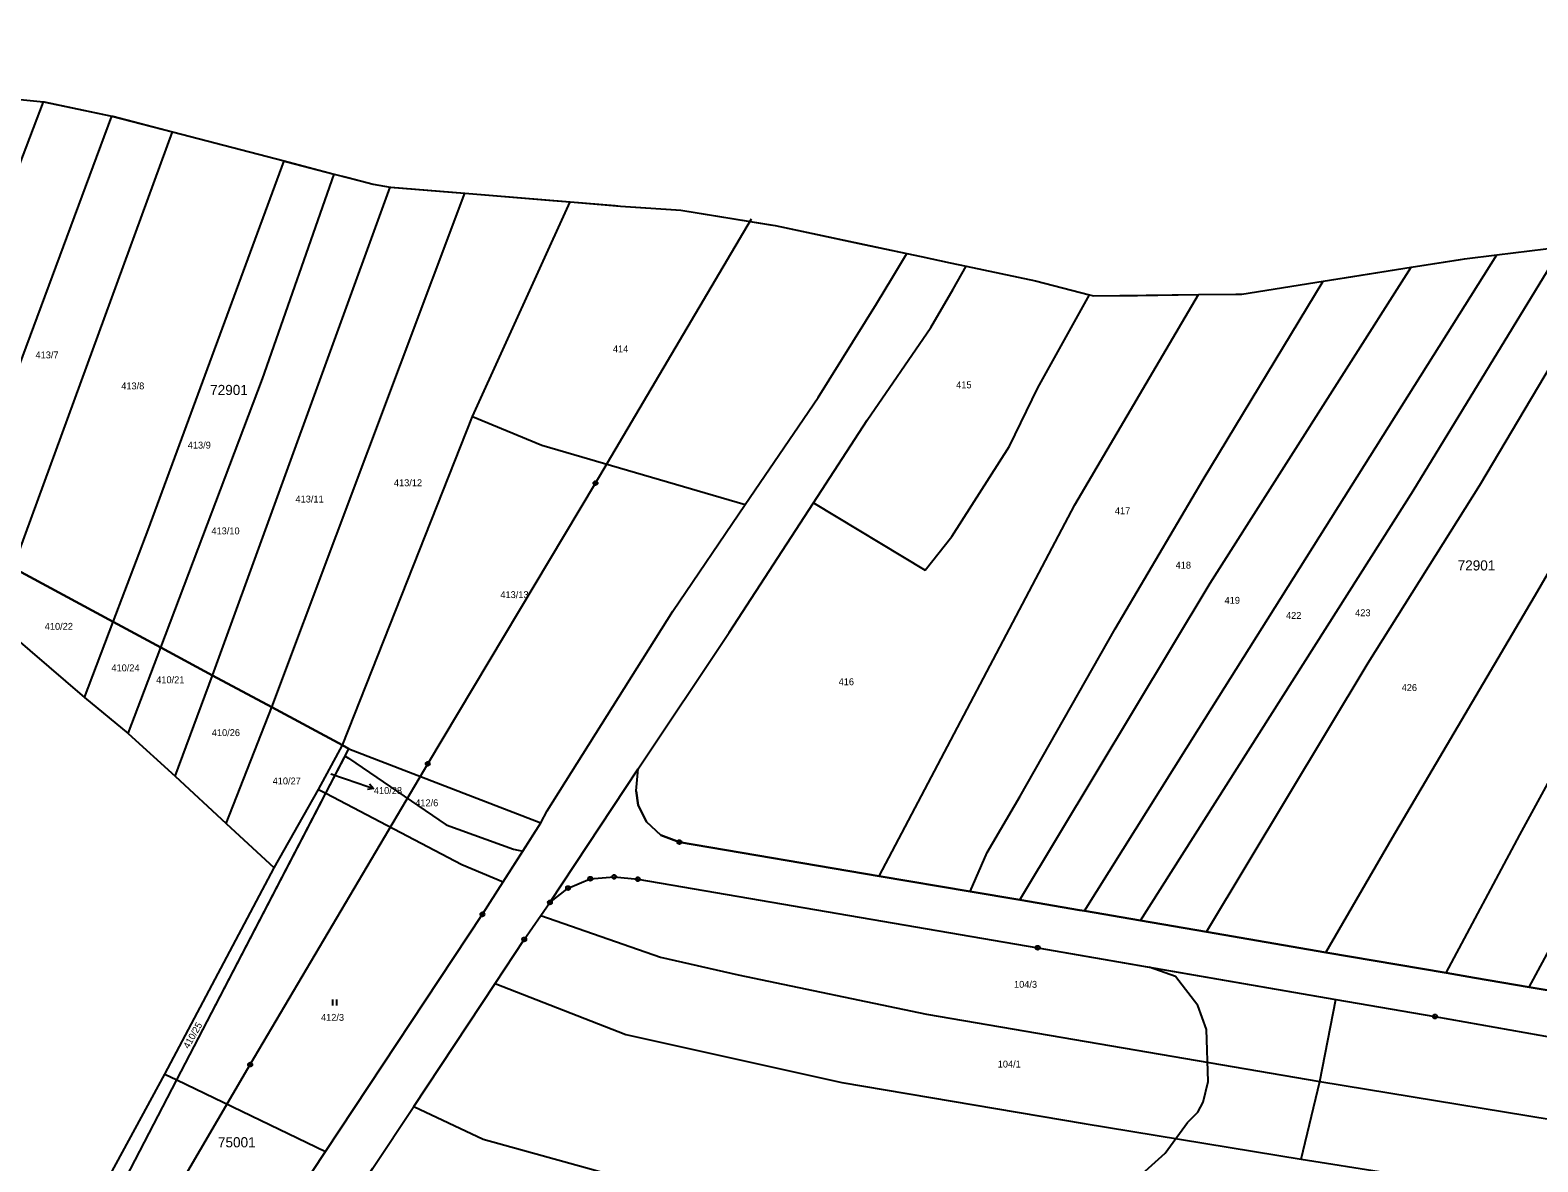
# Model space of a CAD drawing. Extents: x -743888 to -742027, y -1128394 to -1126768.
# Drawn here: x -743633.6 to -743261.6, y -1127120.7 to -1126841.6 of the extents above; entities that cross this region are included whole.
import ezdxf

# ---------------------------------------------------------------- set-up
doc = ezdxf.new("R2010")
doc.units = 0
for name, color, linetype in [('Vrstva 1', 7, 'Continuous'), ('Vrstva 12', 7, 'Continuous'), ('Vrstva 13', 7, 'Continuous'), ('Vrstva 16', 7, 'Continuous'), ('Vrstva 18', 7, 'Continuous'), ('Vrstva 24', 7, 'Continuous'), ('Vrstva 25', 7, 'Continuous'), ('Vrstva 26', 7, 'Continuous'), ('Vrstva 52', 7, 'Continuous'), ('Vrstva 53', 7, 'Continuous'), ('Vrstva 6', 7, 'Continuous')]:
    doc.layers.add(name, color=color, linetype=linetype)

msp = doc.modelspace()

# ---------------------------------------------------------------- linework, layer by layer
at = {"layer": 'Vrstva 1'}
for points in [[(-743420.79, -1126902.49), (-743417.33, -1126896.72)], [(-743405.93, -1126905.47), (-743402.66, -1126899.83)], [(-743424.78, -1126909.13), (-743420.79, -1126902.49)], [(-743411.38, -1126914.91), (-743405.93, -1126905.47)], [(-743439.2, -1126932.19), (-743424.78, -1126909.13)], [(-743427.08, -1126937.82), (-743411.38, -1126914.91)], [(-743457.17, -1126958.62), (-743439.2, -1126932.19)], [(-743440.35, -1126958.18), (-743427.08, -1126937.82)], [(-743475.03, -1126984.89), (-743457.17, -1126958.62)], [(-743461.19, -1126990.18), (-743440.35, -1126958.18)], [(-743637.84, -1126974.2), (-743613.12, -1126987.52)], [(-743506.07, -1127034.13), (-743475.03, -1126984.89)], [(-743613.12, -1126987.52), (-743601.38, -1126993.85)], [(-743483.62, -1127023.79), (-743461.19, -1126990.18)], [(-743601.38, -1126993.85), (-743588.59, -1127000.75)], [(-743588.59, -1127000.75), (-743573.98, -1127008.62)], [(-743573.98, -1127008.62), (-743556.57, -1127018)], [(-743560.68, -1127029.82), (-743554.98, -1127018.86)], [(-743556.57, -1127018), (-743554.98, -1127018.86)], [(-743554.98, -1127018.86), (-743507.61, -1127037.13)], [(-743505.37, -1127056.75), (-743483.62, -1127023.79)], [(-743484.09, -1127029.22), (-743483.62, -1127023.79)], [(-743597.45, -1127100.54), (-743560.68, -1127029.82)], [(-743484.09, -1127029.22), (-743483.64, -1127032.8)], [(-743483.64, -1127032.8), (-743481.55, -1127036.83)], [(-743516.89, -1127051.64), (-743507.61, -1127037.13)], [(-743507.61, -1127037.13), (-743506.07, -1127034.13)], [(-743481.55, -1127036.83), (-743477.98, -1127040.17)], [(-743477.98, -1127040.17), (-743473.44, -1127041.87)], [(-743473.44, -1127041.87), (-743424.12, -1127050.25)], [(-743522.03, -1127059.68), (-743516.89, -1127051.64)], [(-743500.91, -1127053.2), (-743495.43, -1127050.9)], [(-743495.43, -1127050.9), (-743489.52, -1127050.44)], [(-743489.52, -1127050.44), (-743483.7, -1127051.01)], [(-743483.7, -1127051.01), (-743385.04, -1127067.93)], [(-743424.12, -1127050.25), (-743401.72, -1127054.05)], [(-743505.37, -1127056.75), (-743500.91, -1127053.2)], [(-743401.72, -1127054.05), (-743389.47, -1127056.13)], [(-743389.47, -1127056.13), (-743374.75, -1127058.63)], [(-743560.72, -1127118.19), (-743522.03, -1127059.68)], [(-743511.71, -1127065.87), (-743507.61, -1127059.97)], [(-743507.61, -1127059.97), (-743505.37, -1127056.75)], [(-743374.75, -1127058.63), (-743373.46, -1127058.85)], [(-743373.46, -1127058.85), (-743359.71, -1127061.21)], [(-743359.71, -1127061.21), (-743343.4, -1127064.01)], [(-743518.91, -1127076.75), (-743511.71, -1127065.87)], [(-743343.4, -1127064.01), (-743313.92, -1127069.06)], [(-743385.04, -1127067.93), (-743311.47, -1127080.65)], [(-743313.92, -1127069.06), (-743284.26, -1127074.14)], [(-743284.26, -1127074.14), (-743277.29, -1127075.34)], [(-743538.97, -1127107.07), (-743518.91, -1127076.75)], [(-743277.29, -1127075.34), (-743263.8, -1127077.63)], [(-743263.8, -1127077.63), (-743251.53, -1127079.71)], [(-743311.47, -1127080.65), (-743287.04, -1127084.88)], [(-743287.04, -1127084.88), (-743198.26, -1127100.66)], [(-743642.12, -1127186.45), (-743597.45, -1127100.54)], [(-743549.04, -1127122.29), (-743538.97, -1127107.07)], [(-743576.94, -1127142.72), (-743560.72, -1127118.19)]]:
    msp.add_lwpolyline(points, dxfattribs=at)
at = {"layer": 'Vrstva 12'}
for points in [[(-743494.14, -1126953.33), (-743455.61, -1126888.13)], [(-743535.51, -1127022.55), (-743494.14, -1126953.33)], [(-743579.34, -1127096.74), (-743535.51, -1127022.55)], [(-743624.66, -1127174.21), (-743579.34, -1127096.74)]]:
    msp.add_lwpolyline(points, dxfattribs=at)
at = {"layer": 'Vrstva 13'}
for points in [[(-743658.2, -1126856.48), (-743630.32, -1126859.26)], [(-743630.32, -1126859.26), (-743626.75, -1126860)], [(-743626.75, -1126860), (-743613.43, -1126862.82)], [(-743613.43, -1126862.82), (-743598.46, -1126866.7)], [(-743598.46, -1126866.7), (-743570.98, -1126873.86)], [(-743570.98, -1126873.86), (-743570.28, -1126874.05)], [(-743570.28, -1126874.05), (-743558.58, -1126877.09)], [(-743558.58, -1126877.09), (-743555.26, -1126877.96)], [(-743555.26, -1126877.96), (-743548.99, -1126879.59)], [(-743548.99, -1126879.59), (-743544.8, -1126880.33)], [(-743544.8, -1126880.33), (-743529.54, -1126881.59)], [(-743529.54, -1126881.59), (-743526.35, -1126881.85)], [(-743526.35, -1126881.85), (-743516.49, -1126882.66)], [(-743516.49, -1126882.66), (-743504.64, -1126883.63)], [(-743504.64, -1126883.63), (-743500.35, -1126883.98)], [(-743500.35, -1126883.98), (-743489.25, -1126884.88)], [(-743489.25, -1126884.88), (-743487.94, -1126884.99)], [(-743487.94, -1126884.99), (-743474.2, -1126885.91)], [(-743474.2, -1126885.91), (-743473.08, -1126885.98)], [(-743473.08, -1126885.98), (-743451, -1126889.6)], [(-743451, -1126889.6), (-743449.81, -1126889.8)], [(-743449.81, -1126889.8), (-743427.91, -1126894.47)], [(-743427.91, -1126894.47), (-743417.33, -1126896.72)], [(-743271.77, -1126897.03), (-743255.64, -1126895.06)], [(-743417.33, -1126896.72), (-743413.79, -1126897.47)], [(-743413.79, -1126897.47), (-743406.62, -1126898.99)], [(-743406.62, -1126898.99), (-743402.66, -1126899.83)], [(-743402.66, -1126899.83), (-743385.6, -1126903.46)], [(-743307.33, -1126902.38), (-743292.9, -1126900.09)], [(-743292.9, -1126900.09), (-743280.74, -1126898.16)], [(-743280.74, -1126898.16), (-743279.71, -1126898)], [(-743279.71, -1126898), (-743271.77, -1126897.03)], [(-743385.6, -1126903.46), (-743372.24, -1126906.89)], [(-743334.69, -1126906.72), (-743314.63, -1126903.54)], [(-743314.63, -1126903.54), (-743307.33, -1126902.38)], [(-743372.24, -1126906.89), (-743371.28, -1126907.14)], [(-743371.28, -1126907.14), (-743360.4, -1126907.02)], [(-743360.4, -1126907.02), (-743345.39, -1126906.84)], [(-743345.39, -1126906.84), (-743336.16, -1126906.74)], [(-743336.16, -1126906.74), (-743334.69, -1126906.72)]]:
    msp.add_lwpolyline(points, dxfattribs=at)
at = {"layer": 'Vrstva 16'}
msp.add_line((-743549.86, -1127027.5), (-743548.88, -1127028.64), dxfattribs=at)
for points in [[(-743559.41, -1127025), (-743552.66, -1127027.33)], [(-743552.66, -1127027.33), (-743548.88, -1127028.64), (-743550.35, -1127028.92)]]:
    msp.add_lwpolyline(points, dxfattribs=at)
at = {"layer": 'Vrstva 24'}
for p, q in [((-743473.49, -1127041.87), (-743473.39, -1127041.87)), ((-743495.48, -1127050.9), (-743495.38, -1127050.9)), ((-743489.57, -1127050.44), (-743489.47, -1127050.44)), ((-743483.75, -1127051.01), (-743483.65, -1127051.01)), ((-743500.96, -1127053.2), (-743500.86, -1127053.2)), ((-743522.08, -1127059.68), (-743521.98, -1127059.68)), ((-743505.42, -1127056.75), (-743505.32, -1127056.75)), ((-743511.76, -1127065.87), (-743511.66, -1127065.87)), ((-743385.09, -1127067.93), (-743384.99, -1127067.93)), ((-743287.09, -1127084.88), (-743286.99, -1127084.88))]:
    msp.add_line(p, q, dxfattribs=at)
for centre in [(-743473.44, -1127041.87), (-743495.43, -1127050.9), (-743489.52, -1127050.44), (-743483.7, -1127051.01), (-743505.37, -1127056.75), (-743500.91, -1127053.2), (-743522.03, -1127059.68), (-743511.71, -1127065.87), (-743385.04, -1127067.93), (-743287.04, -1127084.88)]:
    msp.add_circle(centre, 0.499, dxfattribs=at)
at = {"layer": 'Vrstva 25'}
for p, q in [((-743558.99, -1127080.68), (-743558.99, -1127082.18)), ((-743557.99, -1127082.18), (-743557.99, -1127080.68))]:
    msp.add_line(p, q, dxfattribs=at)
at = {"layer": 'Vrstva 26'}
for p, q in [((-743494.6, -1126953.51), (-743493.95, -1126952.87)), ((-743494.34, -1126953.78), (-743493.69, -1126953.13)), ((-743535.97, -1127022.73), (-743535.33, -1127022.09)), ((-743535.71, -1127023), (-743535.06, -1127022.35)), ((-743579.8, -1127096.92), (-743579.16, -1127096.28)), ((-743579.54, -1127097.19), (-743578.89, -1127096.54))]:
    msp.add_line(p, q, dxfattribs=at)
for centre in [(-743494.14, -1126953.33), (-743535.51, -1127022.55), (-743579.34, -1127096.74)]:
    msp.add_circle(centre, 0.5, dxfattribs=at)
at = {"layer": 'Vrstva 52'}
for points in [[(-743555.91, -1127020.65), (-743554.98, -1127018.86), (-743556.57, -1127018), (-743573.98, -1127008.62), (-743588.59, -1127000.75), (-743601.38, -1126993.85), (-743613.12, -1126987.52), (-743637.84, -1126974.2), (-743652.05, -1126966.54), (-743667.9, -1126958), (-743678.11, -1126952.5), (-743686.33, -1126948.07), (-743692.02, -1126945.79), (-743692.45, -1126945.62), (-743741.88, -1126925.86), (-743742.99, -1126927.29), (-743798.75, -1126999.39), (-743813.51, -1126987.67), (-743763.23, -1126919.95), (-743762.33, -1126918.74), (-743791.08, -1126908.6), (-743783.35, -1126864.33), (-743779.39, -1126841.61)], [(-743658.2, -1126856.48), (-743630.32, -1126859.26), (-743630.15, -1126859.28), (-743613.43, -1126862.82), (-743613.22, -1126862.86), (-743598.46, -1126866.7), (-743570.98, -1126873.86), (-743558.58, -1126877.09), (-743548.99, -1126879.59), (-743544.8, -1126880.33), (-743544.63, -1126880.36), (-743526.35, -1126881.85), (-743500.35, -1126883.98), (-743487.94, -1126884.99), (-743473.08, -1126885.98), (-743449.81, -1126889.8), (-743417.33, -1126896.72)], [(-743402.66, -1126899.83), (-743385.6, -1126903.46), (-743372.24, -1126906.89), (-743371.28, -1126907.14), (-743345.39, -1126906.84), (-743334.69, -1126906.72), (-743314.63, -1126903.54), (-743292.9, -1126900.09), (-743279.71, -1126898), (-743271.77, -1126897.03), (-743255.64, -1126895.06), (-743252.8, -1126894.71), (-743239.29, -1126892.07), (-743209.04, -1126886.14), (-743183.51, -1126881.14)], [(-743512.05, -1127044.08), (-743507.61, -1127037.13), (-743506.07, -1127034.13), (-743475.03, -1126984.89), (-743457.17, -1126958.62), (-743439.2, -1126932.19), (-743424.78, -1126909.13), (-743420.79, -1126902.49), (-743417.33, -1126896.72)], [(-743251.53, -1127079.71), (-743263.8, -1127077.63), (-743277.29, -1127075.34), (-743284.26, -1127074.14), (-743313.92, -1127069.06), (-743343.4, -1127064.01), (-743359.71, -1127061.21), (-743373.46, -1127058.85), (-743374.75, -1127058.63), (-743389.47, -1127056.13), (-743401.72, -1127054.05), (-743424.12, -1127050.25), (-743473.44, -1127041.87), (-743477.98, -1127040.17), (-743481.55, -1127036.83), (-743483.64, -1127032.8), (-743484.09, -1127029.22), (-743483.62, -1127023.79), (-743461.19, -1126990.18), (-743440.35, -1126958.18), (-743427.08, -1126937.82), (-743411.38, -1126914.91), (-743405.93, -1126905.47), (-743402.66, -1126899.83)], [(-743677.39, -1127227.76), (-743671.64, -1127230.23), (-743666.12, -1127232.6), (-743642.12, -1127186.45), (-743597.45, -1127100.54), (-743561.27, -1127030.96), (-743560.68, -1127029.82), (-743555.91, -1127020.65)], [(-743555.91, -1127020.65), (-743555.06, -1127021.13), (-743530.94, -1127037.63), (-743514.38, -1127043.63), (-743512.05, -1127044.08)], [(-743646.21, -1127246.53), (-743643.98, -1127243.27), (-743636.37, -1127232.18), (-743616.38, -1127202.08), (-743576.94, -1127142.72), (-743560.72, -1127118.19), (-743522.03, -1127059.68), (-743516.89, -1127051.64), (-743512.05, -1127044.08)], [(-743632.18, -1127248.58), (-743629.87, -1127244.98), (-743628.48, -1127242.82), (-743621.98, -1127232.71), (-743610.18, -1127214.83), (-743593.92, -1127190.2), (-743584.02, -1127175.2), (-743567.27, -1127149.84), (-743566.89, -1127149.27), (-743558.76, -1127136.98), (-743549.04, -1127122.29), (-743538.97, -1127107.07), (-743518.91, -1127076.75), (-743511.71, -1127065.87), (-743507.61, -1127059.97), (-743505.37, -1127056.75), (-743500.91, -1127053.2), (-743495.43, -1127050.9), (-743489.52, -1127050.44), (-743483.7, -1127051.01), (-743385.04, -1127067.93), (-743357.57, -1127072.68)], [(-743632.18, -1127248.58), (-743628.94, -1127248.88), (-743600.06, -1127248), (-743578.88, -1127244.63), (-743552.13, -1127239.63), (-743510.56, -1127223.5), (-743490.63, -1127213.25), (-743365.06, -1127128.88), (-743353.56, -1127118.63), (-743348.06, -1127111), (-743345.5, -1127108.5), (-743344.25, -1127106), (-743343, -1127100.88), (-743343.38, -1127088.13), (-743345.5, -1127082.13), (-743351.06, -1127075), (-743357.57, -1127072.68)], [(-743357.57, -1127072.68), (-743311.47, -1127080.65), (-743287.04, -1127084.88), (-743198.26, -1127100.66)]]:
    msp.add_lwpolyline(points, dxfattribs=at)
at = {"layer": 'Vrstva 6'}
for points in [[(-743667.9, -1126958), (-743630.32, -1126859.26)], [(-743652.05, -1126966.54), (-743613.43, -1126862.82)], [(-743637.84, -1126974.2), (-743598.46, -1126866.7)], [(-743604.54, -1126964.89), (-743570.98, -1126873.86)], [(-743576.26, -1126927.6), (-743558.58, -1126877.09)], [(-743588.59, -1127000.75), (-743544.8, -1126880.33)], [(-743573.98, -1127008.62), (-743526.35, -1126881.85)], [(-743524.49, -1126936.89), (-743500.35, -1126883.98)], [(-743275.93, -1126953.86), (-743239.29, -1126892.07)], [(-743292.37, -1126955.23), (-743255.64, -1126895.06)], [(-743345.29, -1127013.85), (-743271.77, -1126897.03)], [(-743342.45, -1126977.97), (-743292.9, -1126900.09)], [(-743344.18, -1126952.46), (-743314.63, -1126903.54)], [(-743384.97, -1126929.79), (-743372.24, -1126906.89)], [(-743375.85, -1126958.71), (-743345.39, -1126906.84)], [(-743266.09, -1127040.1), (-743193, -1126906.14)], [(-743601.38, -1126993.85), (-743576.26, -1126927.6)], [(-743392, -1126944.18), (-743384.97, -1126929.79)], [(-743556.57, -1127018), (-743524.49, -1126936.89)], [(-743524.49, -1126936.89), (-743507.35, -1126943.98)], [(-743261.68, -1126979.9), (-743236.45, -1126936.5)], [(-743507.35, -1126943.98), (-743457.17, -1126958.62)], [(-743406.19, -1126966.46), (-743392, -1126944.18)], [(-743365.92, -1126989.29), (-743344.18, -1126952.46)], [(-743359.71, -1127061.21), (-743292.37, -1126955.23)], [(-743303.47, -1126997.62), (-743275.93, -1126953.86)], [(-743440.35, -1126958.18), (-743412.83, -1126974.8)], [(-743424.12, -1127050.25), (-743375.85, -1126958.71)], [(-743613.12, -1126987.52), (-743604.54, -1126964.89)], [(-743412.83, -1126974.8), (-743406.19, -1126966.46)], [(-743389.47, -1127056.13), (-743342.45, -1126977.97)], [(-743297.49, -1127040.77), (-743261.68, -1126979.9)], [(-743642.55, -1126987.04), (-743620.19, -1127006.18)], [(-743620.19, -1127006.18), (-743613.12, -1126987.52)], [(-743389.37, -1127030.54), (-743365.92, -1126989.29)], [(-743609.42, -1127015.07), (-743601.38, -1126993.85)], [(-743343.4, -1127064.01), (-743303.47, -1126997.62)], [(-743597.86, -1127025.57), (-743588.59, -1127000.75)], [(-743620.19, -1127006.18), (-743609.42, -1127015.07)], [(-743585.23, -1127037.3), (-743573.98, -1127008.62)], [(-743609.42, -1127015.07), (-743597.86, -1127025.57)], [(-743373.46, -1127058.85), (-743345.29, -1127013.85)], [(-743562.48, -1127028.88), (-743556.57, -1127018)], [(-743597.86, -1127025.57), (-743585.23, -1127037.3)], [(-743573.39, -1127048.24), (-743562.48, -1127028.88)], [(-743562.48, -1127028.88), (-743560.68, -1127029.82)], [(-743560.68, -1127029.82), (-743527.15, -1127047.39)], [(-743397.47, -1127044.4), (-743389.37, -1127030.54)], [(-743585.23, -1127037.3), (-743573.39, -1127048.24)], [(-743313.92, -1127069.06), (-743297.49, -1127040.77)], [(-743284.26, -1127074.14), (-743266.09, -1127040.1)], [(-743401.72, -1127054.05), (-743397.47, -1127044.4)], [(-743600.41, -1127099.12), (-743573.39, -1127048.24)], [(-743527.15, -1127047.39), (-743516.89, -1127051.64)], [(-743263.8, -1127077.63), (-743246.71, -1127046.03)], [(-743507.61, -1127059.97), (-743478.13, -1127070.26)], [(-743478.13, -1127070.26), (-743458.97, -1127074.63)], [(-743458.97, -1127074.63), (-743412.49, -1127084.27)], [(-743518.91, -1127076.75), (-743486.65, -1127089.31)], [(-743315.45, -1127100.94), (-743311.47, -1127080.65)], [(-743412.49, -1127084.27), (-743315.45, -1127100.94)], [(-743486.65, -1127089.31), (-743433.39, -1127101.15)], [(-743646.48, -1127183.8), (-743600.41, -1127099.12)], [(-743600.41, -1127099.12), (-743597.45, -1127100.54)], [(-743597.45, -1127100.54), (-743560.72, -1127118.19)], [(-743320.04, -1127120.06), (-743315.45, -1127100.94)], [(-743315.45, -1127100.94), (-743241.34, -1127113.11)], [(-743433.39, -1127101.15), (-743373.57, -1127111.3)], [(-743538.97, -1127107.07), (-743521.87, -1127115.17)], [(-743373.57, -1127111.3), (-743320.04, -1127120.06)], [(-743521.87, -1127115.17), (-743485.93, -1127125.07)], [(-743320.04, -1127120.06), (-743257.58, -1127129.9)]]:
    msp.add_lwpolyline(points, dxfattribs=at)

# ---------------------------------------------------------------- texts
at = {"layer": 'Vrstva 16'}
msp.add_text('410/28', height=1.7, dxfattribs=at).set_placement((-743548.82, -1127030.01))
at = {"layer": 'Vrstva 18'}
for s, height, p in [('413/7', 1.7, (-743632.29, -1126922.56)), ('414', 1.7, (-743489.84, -1126921.08)), ('413/8', 1.7, (-743611.14, -1126930.21)), ('415', 1.7, (-743405.15, -1126929.93)), ('413/9', 1.7, (-743594.73, -1126944.81)), ('413/12', 1.7, (-743543.87, -1126954.09)), ('413/11', 1.7, (-743568.15, -1126958.11)), ('417', 1.7, (-743365.99, -1126960.99)), ('413/10', 1.7, (-743588.89, -1126965.97)), ('418', 1.7, (-743351.01, -1126974.41)), ('413/13', 1.7, (-743517.6, -1126981.69)), ('419', 1.7, (-743338.93, -1126983.08)), ('422', 1.7, (-743323.78, -1126986.82)), ('423', 1.7, (-743306.71, -1126986.15)), ('410/22', 1.7, (-743630.01, -1126989.5)), ('410/24', 1.7, (-743613.57, -1126999.75)), ('410/21', 1.7, (-743602.51, -1127002.69)), ('416', 1.7, (-743434.15, -1127003.17)), ('426', 1.7, (-743295.25, -1127004.6)), ('410/26', 1.7, (-743588.8, -1127015.72)), ('410/27', 1.7, (-743573.79, -1127027.64)), ('410/28', 0.1, (-743559.41, -1127025)), ('412/6', 1.7, (-743538.61, -1127033.04)), ('104/3', 1.7, (-743390.88, -1127077.8)), ('412/3', 1.7, (-743561.86, -1127085.95)), ('104/1', 1.7, (-743394.9, -1127097.47))]:
    msp.add_text(s, height=height, dxfattribs=at).set_placement(p)
msp.add_text('410/25', height=1.7, rotation=60.3483, dxfattribs=at).set_placement((-743594.5, -1127092.97))
at = {"layer": 'Vrstva 53'}
for s, p in [('72901', (-743589.21, -1126931.6)), ('72901', (-743281.43, -1126974.87)), ('75001', (-743587.28, -1127117.15))]:
    msp.add_text(s, height=2.5, dxfattribs=at).set_placement(p)

doc.saveas('drawing.dxf')
